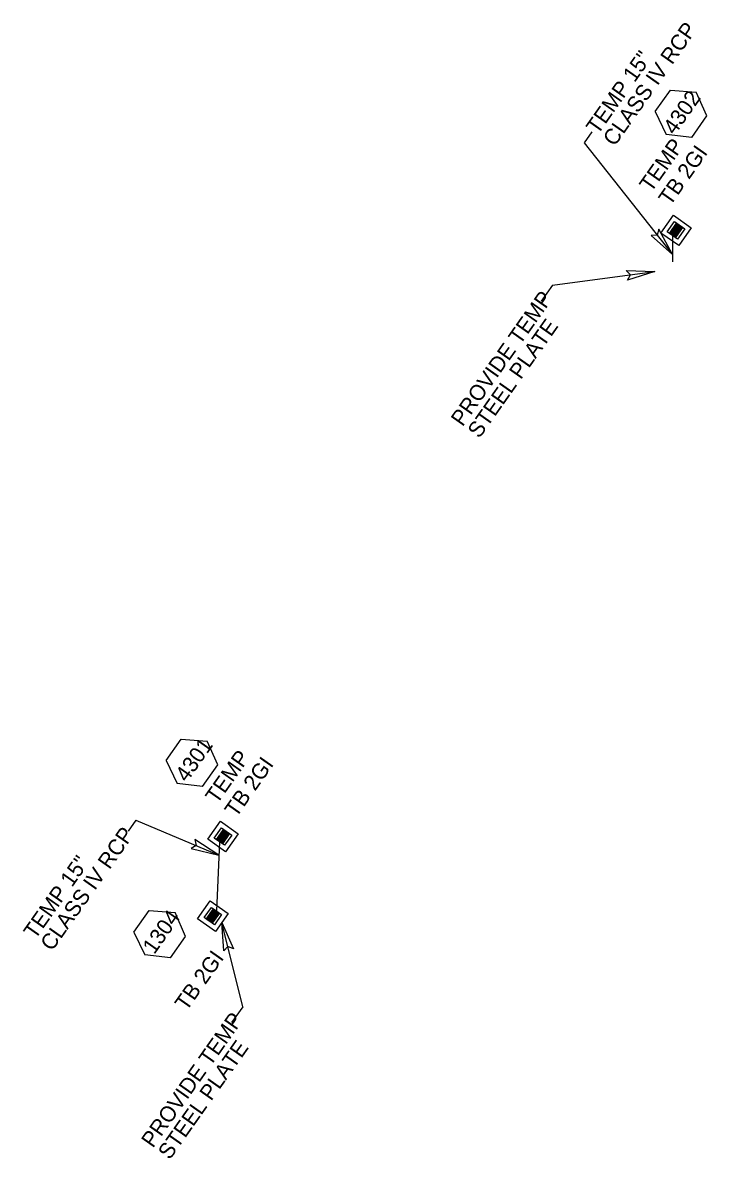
# Model space of a CAD drawing. Extents: x 2214419 to 2238519, y 983271 to 1015868.
# Drawn here: x 2216735.8 to 2216954.8, y 986575.7 to 986939.2 of the extents above; entities that cross this region are included whole.
import ezdxf

# ---------------------------------------------------------------- set-up
doc = ezdxf.new("R2010")
doc.units = 0
for name, color, linetype in [('Prop Drainage Structure Box Number Symbol CELL', 7, 'Continuous'), ('Prop Drainage Structure Drop Inlet Grate 2 Wide Slots and Sag Grates 840 22 TB CELL', 7, 'Continuous'), ('Prop Drainage Structure Drop Inlet Grate 2 Wide Slots and Sag Grates 840 22 TB Label', 7, 'Continuous'), ('Prop Drainage Structure Pipe Alternate 15in', 7, 'Continuous'), ('Prop Drainage Structure Pipe RCP 15in Class IV', 7, 'Continuous'), ('Prop Drainage Structure Plot Symbol 20 Scale', 7, 'Continuous'), ('Prop Drainage Structure Plot Symbol 50 Scale', 7, 'Continuous'), ('Prop Plan Preparation Drainage Notes Label', 7, 'Continuous')]:
    doc.layers.add(name, color=color, linetype=linetype)

msp = doc.modelspace()

# ---------------------------------------------------------------- linework, layer by layer
at = {"layer": 'Prop Drainage Structure Box Number Symbol CELL'}
for p, q in [((2216938.16, 986910.8), (2216942.99, 986917.67)), ((2216942.99, 986917.67), (2216951.29, 986917.04)), ((2216954.66, 986909.44), (2216951.29, 986917.04)), ((2216938.16, 986910.8), (2216941.67, 986903.53)), ((2216949.82, 986902.58), (2216954.66, 986909.44)), ((2216949.82, 986902.58), (2216941.67, 986903.53)), ((2216781.69, 986703.24), (2216786.53, 986710.1)), ((2216786.53, 986710.1), (2216794.82, 986709.48)), ((2216798.2, 986701.88), (2216794.82, 986709.48)), ((2216781.69, 986703.24), (2216785.21, 986695.96)), ((2216793.36, 986695.01), (2216798.2, 986701.88)), ((2216793.36, 986695.01), (2216785.21, 986695.96)), ((2216771.38, 986648.39), (2216776.22, 986655.26)), ((2216776.22, 986655.26), (2216784.52, 986654.63)), ((2216787.89, 986647.03), (2216784.52, 986654.63)), ((2216771.38, 986648.39), (2216774.9, 986641.12)), ((2216783.05, 986640.17), (2216787.89, 986647.03)), ((2216783.05, 986640.17), (2216774.9, 986641.12))]:
    msp.add_line(p, q, dxfattribs=at)
at = {"layer": 'Prop Drainage Structure Drop Inlet Grate 2 Wide Slots and Sag Grates 840 22 TB CELL'}
for p, q in [((2216945.96, 986874.46), (2216945.96, 986874.46)), ((2216943.65, 986871.19), (2216943.65, 986871.19)), ((2216943.85, 986873.5), (2216943.85, 986873.5)), ((2216944.81, 986872.82), (2216944.81, 986872.82)), ((2216945.76, 986872.15), (2216945.76, 986872.15)), ((2216798.91, 986679.62), (2216798.91, 986679.62)), ((2216799.86, 986678.95), (2216799.86, 986678.95)), ((2216800.82, 986678.27), (2216800.82, 986678.27)), ((2216801.01, 986680.58), (2216801.01, 986680.58)), ((2216798.71, 986677.31), (2216798.71, 986677.31)), ((2216795.69, 986654.18), (2216795.69, 986654.18)), ((2216796.64, 986653.5), (2216796.64, 986653.5)), ((2216797.59, 986652.83), (2216797.59, 986652.83)), ((2216797.79, 986655.14), (2216797.79, 986655.14)), ((2216795.49, 986651.87), (2216795.49, 986651.87))]:
    msp.add_line(p, q, dxfattribs=at)
for points in [[(2216946.91, 986873.79), (2216944.61, 986870.52), (2216942.7, 986871.86), (2216945, 986875.13), (2216946.91, 986873.79)], [(2216946.82, 986873.77), (2216944.59, 986870.6), (2216942.79, 986871.88), (2216945.02, 986875.04), (2216946.82, 986873.77), (2216946.82, 986873.77)], [(2216946.81, 986873.77), (2216945.71, 986872.2), (2216943.92, 986873.46), (2216945.02, 986875.03), (2216946.81, 986873.77)], [(2216944.82, 986873.95), (2216944.34, 986873.27), (2216944.12, 986873.42), (2216944.6, 986874.1), (2216944.82, 986873.95)], [(2216945.35, 986874.7), (2216944.87, 986874.01), (2216944.65, 986874.17), (2216945.13, 986874.85), (2216945.35, 986874.7)], [(2216945.66, 986874.47), (2216945.18, 986873.79), (2216944.96, 986873.95), (2216945.44, 986874.63), (2216945.66, 986874.47)], [(2216945.98, 986874.25), (2216945.5, 986873.57), (2216945.28, 986873.73), (2216945.76, 986874.41), (2216945.98, 986874.25)], [(2216946.29, 986874.03), (2216945.81, 986873.35), (2216945.59, 986873.5), (2216946.07, 986874.19), (2216946.29, 986874.03)], [(2216945.69, 986872.18), (2216944.59, 986870.62), (2216942.8, 986871.88), (2216943.91, 986873.44), (2216945.69, 986872.18)], [(2216943.7, 986872.36), (2216943.22, 986871.68), (2216943, 986871.84), (2216943.48, 986872.52), (2216943.7, 986872.36)], [(2216944.02, 986872.14), (2216943.54, 986871.46), (2216943.32, 986871.62), (2216943.8, 986872.3), (2216944.02, 986872.14)], [(2216944.23, 986873.11), (2216943.75, 986872.43), (2216943.53, 986872.59), (2216944.01, 986873.27), (2216944.23, 986873.11)], [(2216944.33, 986871.92), (2216943.85, 986871.24), (2216943.63, 986871.39), (2216944.11, 986872.08), (2216944.33, 986871.92)], [(2216944.55, 986872.89), (2216944.07, 986872.21), (2216943.85, 986872.37), (2216944.33, 986873.05), (2216944.55, 986872.89)], [(2216944.65, 986871.7), (2216944.17, 986871.02), (2216943.95, 986871.17), (2216944.43, 986871.85), (2216944.65, 986871.7)], [(2216944.86, 986872.67), (2216944.38, 986871.99), (2216944.16, 986872.14), (2216944.64, 986872.82), (2216944.86, 986872.67)], [(2216944.96, 986871.48), (2216944.48, 986870.79), (2216944.26, 986870.95), (2216944.74, 986871.63), (2216944.96, 986871.48)], [(2216945.14, 986873.72), (2216944.66, 986873.04), (2216944.43, 986873.2), (2216944.91, 986873.88), (2216945.14, 986873.72)], [(2216945.18, 986872.45), (2216944.7, 986871.77), (2216944.48, 986871.92), (2216944.96, 986872.6), (2216945.18, 986872.45)], [(2216945.45, 986873.5), (2216944.97, 986872.82), (2216944.75, 986872.98), (2216945.23, 986873.66), (2216945.45, 986873.5)], [(2216945.49, 986872.22), (2216945.01, 986871.54), (2216944.79, 986871.7), (2216945.27, 986872.38), (2216945.49, 986872.22)], [(2216945.77, 986873.28), (2216945.29, 986872.6), (2216945.06, 986872.76), (2216945.54, 986873.44), (2216945.77, 986873.28)], [(2216946.08, 986873.06), (2216945.6, 986872.38), (2216945.38, 986872.53), (2216945.86, 986873.21), (2216946.08, 986873.06)], [(2216946.61, 986873.81), (2216946.13, 986873.13), (2216945.91, 986873.28), (2216946.39, 986873.96), (2216946.61, 986873.81)], [(2216801.97, 986679.91), (2216799.66, 986676.64), (2216797.76, 986677.98), (2216800.06, 986681.25), (2216801.97, 986679.91)], [(2216801.88, 986679.89), (2216799.65, 986676.73), (2216797.84, 986678), (2216800.08, 986681.17), (2216801.88, 986679.89), (2216801.88, 986679.89)], [(2216800.75, 986678.31), (2216799.65, 986676.74), (2216797.86, 986678), (2216798.96, 986679.57), (2216800.75, 986678.31)], [(2216798.76, 986678.49), (2216798.28, 986677.81), (2216798.06, 986677.96), (2216798.54, 986678.64), (2216798.76, 986678.49)], [(2216799.08, 986678.26), (2216798.6, 986677.58), (2216798.37, 986677.74), (2216798.85, 986678.42), (2216799.08, 986678.26)], [(2216799.29, 986679.24), (2216798.81, 986678.55), (2216798.59, 986678.71), (2216799.07, 986679.39), (2216799.29, 986679.24)], [(2216799.39, 986678.04), (2216798.91, 986677.36), (2216798.69, 986677.52), (2216799.17, 986678.2), (2216799.39, 986678.04)], [(2216799.6, 986679.01), (2216799.12, 986678.33), (2216798.9, 986678.49), (2216799.38, 986679.17), (2216799.6, 986679.01)], [(2216801.87, 986679.89), (2216800.76, 986678.32), (2216798.97, 986679.59), (2216800.08, 986681.15), (2216801.87, 986679.89)], [(2216799.71, 986677.82), (2216799.23, 986677.14), (2216799, 986677.3), (2216799.48, 986677.98), (2216799.71, 986677.82)], [(2216799.88, 986680.07), (2216799.4, 986679.39), (2216799.18, 986679.55), (2216799.66, 986680.23), (2216799.88, 986680.07)], [(2216799.92, 986678.79), (2216799.44, 986678.11), (2216799.22, 986678.27), (2216799.7, 986678.95), (2216799.92, 986678.79)], [(2216800.19, 986679.85), (2216799.71, 986679.17), (2216799.49, 986679.32), (2216799.97, 986680), (2216800.19, 986679.85)], [(2216800.23, 986678.57), (2216799.75, 986677.89), (2216799.53, 986678.04), (2216800.01, 986678.73), (2216800.23, 986678.57)], [(2216800.4, 986680.82), (2216799.92, 986680.14), (2216799.7, 986680.29), (2216800.18, 986680.98), (2216800.4, 986680.82)], [(2216800.51, 986679.63), (2216800.03, 986678.95), (2216799.81, 986679.1), (2216800.29, 986679.78), (2216800.51, 986679.63)], [(2216800.55, 986678.35), (2216800.07, 986677.67), (2216799.85, 986677.82), (2216800.33, 986678.5), (2216800.55, 986678.35)], [(2216800.72, 986680.6), (2216800.24, 986679.92), (2216800.02, 986680.07), (2216800.5, 986680.75), (2216800.72, 986680.6)], [(2216800.82, 986679.4), (2216800.34, 986678.72), (2216800.12, 986678.88), (2216800.6, 986679.56), (2216800.82, 986679.4)], [(2216801.03, 986680.38), (2216800.55, 986679.69), (2216800.33, 986679.85), (2216800.81, 986680.53), (2216801.03, 986680.38)], [(2216801.14, 986679.18), (2216800.66, 986678.5), (2216800.44, 986678.66), (2216800.92, 986679.34), (2216801.14, 986679.18)], [(2216801.35, 986680.15), (2216800.87, 986679.47), (2216800.65, 986679.63), (2216801.13, 986680.31), (2216801.35, 986680.15)], [(2216801.66, 986679.93), (2216801.18, 986679.25), (2216800.96, 986679.41), (2216801.44, 986680.09), (2216801.66, 986679.93)], [(2216800.02, 986677.6), (2216799.54, 986676.92), (2216799.32, 986677.07), (2216799.8, 986677.75), (2216800.02, 986677.6)], [(2216794.53, 986652.54), (2216796.84, 986655.81), (2216798.75, 986654.47), (2216796.44, 986651.2), (2216794.53, 986652.54)], [(2216794.62, 986652.56), (2216796.85, 986655.72), (2216798.66, 986654.45), (2216796.43, 986651.28), (2216794.62, 986652.56), (2216794.62, 986652.56)], [(2216794.64, 986652.56), (2216795.74, 986654.13), (2216797.53, 986652.87), (2216796.42, 986651.3), (2216794.64, 986652.56)], [(2216794.84, 986652.52), (2216795.32, 986653.2), (2216795.54, 986653.04), (2216795.06, 986652.36), (2216794.84, 986652.52)], [(2216795.15, 986652.3), (2216795.63, 986652.98), (2216795.85, 986652.82), (2216795.37, 986652.14), (2216795.15, 986652.3)], [(2216795.36, 986653.27), (2216795.85, 986653.95), (2216796.07, 986653.79), (2216795.59, 986653.11), (2216795.36, 986653.27)], [(2216795.47, 986652.08), (2216795.95, 986652.76), (2216796.17, 986652.6), (2216795.69, 986651.92), (2216795.47, 986652.08)], [(2216795.68, 986653.05), (2216796.16, 986653.73), (2216796.38, 986653.57), (2216795.9, 986652.89), (2216795.68, 986653.05)], [(2216795.75, 986654.14), (2216796.86, 986655.71), (2216798.64, 986654.45), (2216797.54, 986652.88), (2216795.75, 986654.14)], [(2216795.78, 986651.85), (2216796.26, 986652.53), (2216796.48, 986652.38), (2216796, 986651.7), (2216795.78, 986651.85)], [(2216795.95, 986654.1), (2216796.43, 986654.78), (2216796.65, 986654.63), (2216796.17, 986653.95), (2216795.95, 986654.1)], [(2216795.99, 986652.82), (2216796.48, 986653.51), (2216796.7, 986653.35), (2216796.22, 986652.67), (2216795.99, 986652.82)], [(2216796.27, 986653.88), (2216796.75, 986654.56), (2216796.97, 986654.41), (2216796.49, 986653.72), (2216796.27, 986653.88)], [(2216796.31, 986652.6), (2216796.79, 986653.28), (2216797.01, 986653.13), (2216796.53, 986652.45), (2216796.31, 986652.6)], [(2216796.48, 986654.85), (2216796.96, 986655.53), (2216797.18, 986655.38), (2216796.7, 986654.7), (2216796.48, 986654.85)], [(2216796.58, 986653.66), (2216797.06, 986654.34), (2216797.28, 986654.18), (2216796.8, 986653.5), (2216796.58, 986653.66)], [(2216796.63, 986652.38), (2216797.11, 986653.06), (2216797.33, 986652.91), (2216796.85, 986652.22), (2216796.63, 986652.38)], [(2216796.8, 986654.63), (2216797.28, 986655.31), (2216797.5, 986655.16), (2216797.02, 986654.47), (2216796.8, 986654.63)], [(2216796.9, 986653.44), (2216797.38, 986654.12), (2216797.6, 986653.96), (2216797.12, 986653.28), (2216796.9, 986653.44)], [(2216797.11, 986654.41), (2216797.59, 986655.09), (2216797.81, 986654.93), (2216797.33, 986654.25), (2216797.11, 986654.41)], [(2216797.21, 986653.21), (2216797.69, 986653.9), (2216797.91, 986653.74), (2216797.43, 986653.06), (2216797.21, 986653.21)], [(2216797.43, 986654.19), (2216797.91, 986654.87), (2216798.13, 986654.71), (2216797.65, 986654.03), (2216797.43, 986654.19)], [(2216797.74, 986653.96), (2216798.22, 986654.64), (2216798.44, 986654.49), (2216797.96, 986653.81), (2216797.74, 986653.96)], [(2216796.1, 986651.63), (2216796.58, 986652.31), (2216796.8, 986652.16), (2216796.32, 986651.48), (2216796.1, 986651.63)]]:
    msp.add_lwpolyline(points, dxfattribs=at)
at = {"layer": 'Prop Drainage Structure Pipe Alternate 15in'}
msp.add_line((2216943.65, 986871.19), (2216943.68, 986862.8), dxfattribs=at)
at = {"layer": 'Prop Drainage Structure Pipe RCP 15in Class IV'}
msp.add_line((2216798.71, 986677.31), (2216797.79, 986655.14), dxfattribs=at)
at = {"layer": 'Prop Drainage Structure Plot Symbol 20 Scale'}
for points in [[(2216947.59, 986873.31), (2216945.29, 986870.04), (2216942.02, 986872.34), (2216944.32, 986875.61)], [(2216802.65, 986679.43), (2216800.34, 986676.16), (2216797.07, 986678.46), (2216799.38, 986681.73)], [(2216793.85, 986653.02), (2216796.16, 986656.29), (2216799.43, 986653.99), (2216797.12, 986650.72)]]:
    msp.add_lwpolyline(points, close=True, dxfattribs=at)
at = {"layer": 'Prop Drainage Structure Plot Symbol 50 Scale'}
for points in [[(2216949.68, 986873.67), (2216945.65, 986867.95), (2216939.93, 986871.98), (2216943.96, 986877.7)], [(2216804.74, 986679.79), (2216800.71, 986674.07), (2216794.98, 986678.1), (2216799.02, 986683.82)], [(2216791.76, 986652.66), (2216795.8, 986658.38), (2216801.52, 986654.35), (2216797.48, 986648.63)]]:
    msp.add_lwpolyline(points, close=True, dxfattribs=at)
at = {"layer": 'Prop Plan Preparation Drainage Notes Label'}
for p, q in [((2216917.84, 986904.3), (2216915.37, 986900.79)), ((2216915.37, 986900.79), (2216943.68, 986865.14)), ((2216905.25, 986855.25), (2216938.02, 986859.63)), ((2216905.25, 986855.25), (2216901.69, 986850.2)), ((2216771.95, 986684.21), (2216769.48, 986680.7)), ((2216771.95, 986684.21), (2216798.53, 986673.05)), ((2216806.19, 986624.51), (2216799.5, 986651.49)), ((2216806.19, 986624.51), (2216802.63, 986619.46))]:
    msp.add_line(p, q, dxfattribs=at)
for points in [[(2216936.87, 986871.23), (2216943.68, 986865.14), (2216939.3, 986873.22), (2216938.76, 986871.33)], [(2216928.89, 986859.98), (2216938.02, 986859.63), (2216929.26, 986856.85), (2216930.19, 986858.59)], [(2216789.64, 986675.1), (2216798.53, 986673.05), (2216790.81, 986678.03), (2216791.25, 986676.11)], [(2216800.16, 986642.38), (2216799.5, 986651.49), (2216803.23, 986643.09), (2216801.4, 986643.82)]]:
    msp.add_lwpolyline(points, close=True, dxfattribs=at)

# ---------------------------------------------------------------- texts
at = {"layer": 'Prop Drainage Structure Box Number Symbol CELL'}
for s, p in [('4302', (2216944.4, 986903.09)), ('4301', (2216788.31, 986696.05)), ('1304', (2216777.87, 986641.02))]:
    msp.add_text(s, height=5, rotation=54.8168, dxfattribs=at).set_placement(p)
at = {"layer": 'Prop Drainage Structure Drop Inlet Grate 2 Wide Slots and Sag Grates 840 22 TB Label'}
for s, p in [('TEMP', (2216936.82, 986884.72)), ('TB 2GI', (2216942.95, 986880.4)), ('TEMP', (2216797.98, 986689.1)), ('TB 2GI', (2216804.11, 986684.78)), ('TB 2GI', (2216788.2, 986622.87))]:
    msp.add_text(s, height=5, rotation=54.8168, dxfattribs=at).set_placement(p)
at = {"layer": 'Prop Plan Preparation Drainage Notes Label'}
for s, rotation, p in [('CLASS IV RCP', 54.8732, (2216925.15, 986899.42)), ('TEMP 15"', 54.8732, (2216919.79, 986903.19)), ('PROVIDE TEMP', 54.8307, (2216876.51, 986809.83)), ('STEEL PLATE', 54.8307, (2216881.87, 986806.05)), ('CLASS IV RCP', 54.8732, (2216745.16, 986642.03)), ('TEMP 15"', 54.8732, (2216739.8, 986645.8)), ('PROVIDE TEMP', 54.8307, (2216777.45, 986579.09)), ('STEEL PLATE', 54.8307, (2216782.81, 986575.31))]:
    msp.add_text(s, height=5, rotation=rotation, dxfattribs=at).set_placement(p)

doc.saveas('drawing.dxf')
